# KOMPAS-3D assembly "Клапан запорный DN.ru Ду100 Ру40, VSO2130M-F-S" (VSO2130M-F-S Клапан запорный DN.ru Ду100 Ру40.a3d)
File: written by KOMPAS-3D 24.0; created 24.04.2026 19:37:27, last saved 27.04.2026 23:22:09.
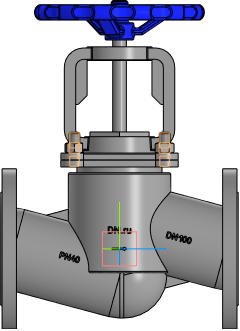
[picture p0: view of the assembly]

Document properties: Автор: DN.ru; Полное имя файла: C:\Работа\ГОТОВЫЕ ИСХОДНИКИ\VSO2130M-F-S Клапан запорный сальниковый DN.ru Ду15-100 Ру40\исходные материалы\DN100\VSO2130M-F-S Клапан запорный DN.ru Ду100 Ру40.a3d

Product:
- Component [detail]: Корпус  | qty 1  | pos. 1  | Масса: 6.9; Автор: R2D2; source file: Korpus.m3d
- Component [detail]: Деталь  | qty 1  | pos. 2  | Масса: 7.950758; Автор: mrdid; source file: rama.m3d
- Component [detail]: Деталь2  | qty 1  | pos. 3  | Масса: 3.344958; Автор: R2D2; additional columns: Типовые; source file: shturval.m3d
- Component [standard]: Шпилька М16-6gx35 ГОСТ 22032-76  | qty 4  | Масса: 0.07017; Раздел спецификации: Стандартные изделия; Рассекать на разрезах: no
- Component [standard]: Гайка М16-6H ГОСТ 5915-70  | qty 4  | Масса: 0.03761; Раздел спецификации: Стандартные изделия; Рассекать на разрезах: no
- Part/product: Клапан запорный DN.ru Ду100 Ру40  | designation VSO2130M-F-S
    Масса: 44
    Раздел спецификации: Прочие изделия
    Примечание: D090-01987

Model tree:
1. Контекстная связь:1  (with: Контекстная связь (Деталь):1)  (labels: Грань.Твердое тело1)
2. Контекстная связь:2  (with: Смещенная плоскость:4, Контекстная связь (Деталь):2)  (labels: Грань.Твердое тело1)
3. Контекстная связь:3  (with: Контекстная связь (Корпус):3)
4. Контекстная связь:4  (with: Эскиз:2, Ребро.Элемент выдавливания:14, Контекстная связь (Деталь):4)
5. Контекстная связь:5  (with: Контекстная связь (Деталь):5)
6. Массив по концентрической сетке:1  (with: Грань.Элемент выдавливания:1, Грань.Элемент выдавливания:15, Грань.Элемент выдавливания:3, Грань.Элемент выдавливания:2, Грань.Элемент выдавливания:16, Грань.Элемент выдавливания:14)  (labels: Грань.Твердое тело1)  (4 pattern instances)
     Шаг 2 = 360; Угол = 9

Referenced files in C:\Работа\ГОТОВЫЕ ИСХОДНИКИ\VSO2130M-F-S Клапан запорный сальниковый DN.ru Ду15-100 Ру40\исходные материалы\DN100\: Korpus.m3d, rama.m3d, shturval.m3d
Referenced files in C:\Program Files\ASCON\KOMPAS-3D v24\Libs\PolynomLib\DATA\vault\Methods\Kompas\3D\: PLib_Stud_1_900.m3d, PLib_Nut_OST92_900.m3d
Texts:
  Крепежное изделие ГОСТ
  BOSimple***PART:d7cea355-acbb-e7a9-246f-9517ee95b2f8***SHORTLOC:Root±30±20±10±120±10±20[Нет;Без покрытия;Без указания материала;-;16;35;2;2]
  BOSimple***PART:17b45fe1-43c8-f41a-5df4-ae57481e6c3b***SHORTLOC:Root±30±10±20±©{}110±10±50±60[Нет;Без покрытия;Без указания материала;-;16;2;24]
  Программные изделия  и базы данных
  VSO2130M-F-S
  Деталь2 Деталь2
  Шпилька М16-6gx35 ГОСТ 22032-76 (1)
  cut1
  Гайка М16-6H ГОСТ 5915-70 (1)
  bcut1
  hole1
  hcut1
  hole2
  Плоскость ZX.Начало координат
  Плоскость XY.Начало координат
  Plane. Начало координат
